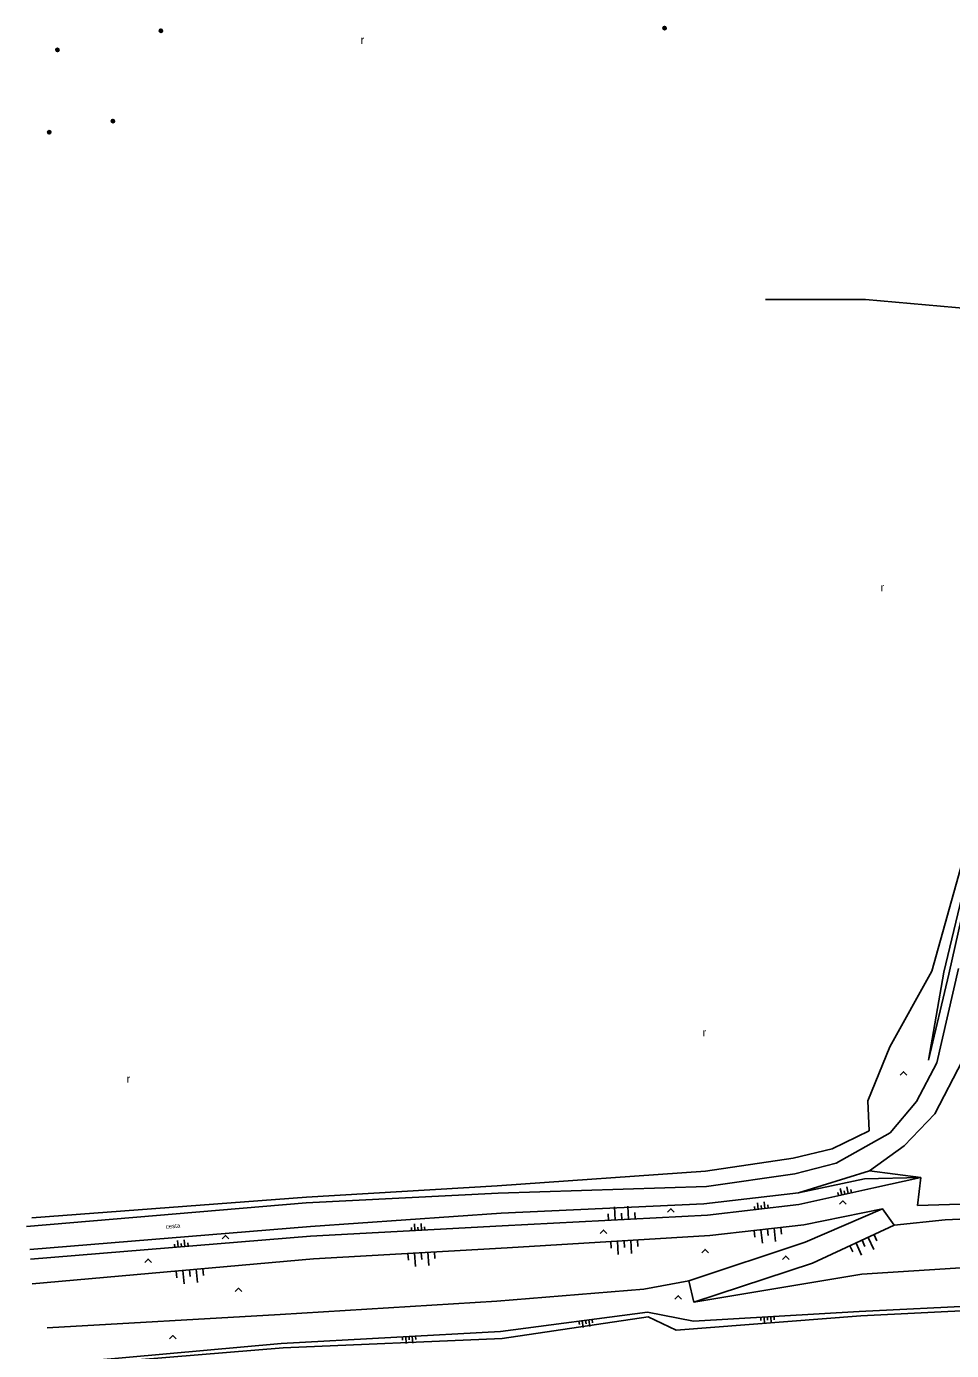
# Model space of a CAD drawing. Extents: x -539515 to -538098, y -1182060 to -1180157.
# Drawn here: x -539389.7 to -539250.9, y -1181057.1 to -1180858.5 of the extents above; entities that cross this region are included whole.
import ezdxf

# ---------------------------------------------------------------- set-up
doc = ezdxf.new("R2010")
doc.units = 0
for name, color, linetype in [('Vrstva 11', 7, 'Continuous'), ('Vrstva 14', 7, 'Continuous'), ('Vrstva 15', 7, 'Continuous'), ('Vrstva 23', 7, 'Continuous'), ('Vrstva 25', 7, 'Continuous'), ('Vrstva 36', 7, 'Continuous'), ('Vrstva 40', 7, 'Continuous')]:
    doc.layers.add(name, color=color, linetype=linetype)

msp = doc.modelspace()

# ---------------------------------------------------------------- linework, layer by layer
at = {"layer": 'Vrstva 11'}
for p, q in [((-539253.09, -1181013.89), (-539249.85, -1180999.75)), ((-539253.41, -1181021.54), (-539249.22, -1181013.54)), ((-539256.16, -1181019.71), (-539253.09, -1181013.89)), ((-539260.07, -1181024.41), (-539256.16, -1181019.71)), ((-539258, -1181026.34), (-539253.41, -1181021.54)), ((-539268.18, -1181028.97), (-539260.07, -1181024.41)), ((-539263.19, -1181030.11), (-539258, -1181026.34)), ((-539274.39, -1181030.54), (-539268.18, -1181028.97)), ((-539287.64, -1181032.44), (-539274.39, -1181030.54)), ((-539273.85, -1181033.4), (-539263.19, -1181030.11)), ((-539263.19, -1181030.11), (-539255.51, -1181031.11)), ((-539255.51, -1181031.11), (-539255.97, -1181035.29)), ((-539347.72, -1181034.93), (-539318.9, -1181033.44)), ((-539318.9, -1181033.44), (-539287.64, -1181032.44)), ((-539288.05, -1181035.06), (-539273.85, -1181033.4)), ((-539389.7, -1181038.45), (-539347.72, -1181034.93)), ((-539318.46, -1181036.45), (-539288.05, -1181035.06)), ((-539255.97, -1181035.29), (-539241.07, -1181034.88)), ((-539347.1, -1181038.48), (-539318.46, -1181036.45)), ((-539389.2, -1181041.91), (-539347.1, -1181038.48))]:
    msp.add_line(p, q, dxfattribs=at)
at = {"layer": 'Vrstva 14'}
for p, q in [((-539251.28, -1181000.64), (-539247.49, -1180983.74)), ((-539248.12, -1180984.08), (-539252.02, -1181000.33)), ((-539252.02, -1181000.33), (-539254.36, -1181013.51)), ((-539254.36, -1181013.51), (-539251.28, -1181000.64)), ((-539273.85, -1181033.4), (-539263.94, -1181031.3)), ((-539263.94, -1181031.3), (-539255.51, -1181031.11)), ((-539255.51, -1181031.11), (-539262.56, -1181032.64)), ((-539262.56, -1181032.64), (-539273.81, -1181035.17)), ((-539273.81, -1181035.17), (-539287.49, -1181036.78)), ((-539287.49, -1181036.78), (-539318.31, -1181038.37)), ((-539273.06, -1181038.22), (-539261.26, -1181035.83)), ((-539261.26, -1181035.83), (-539272.83, -1181040.81)), ((-539261.26, -1181035.83), (-539259.47, -1181038.28)), ((-539251.86, -1181037.44), (-539241.41, -1181036.99)), ((-539318.31, -1181038.37), (-539347.06, -1181039.92)), ((-539287.13, -1181039.82), (-539273.06, -1181038.22)), ((-539271.73, -1181043.97), (-539259.47, -1181038.28)), ((-539259.47, -1181038.28), (-539251.86, -1181037.44)), ((-539347.06, -1181039.92), (-539389.11, -1181043.35)), ((-539317.57, -1181041.64), (-539287.13, -1181039.82)), ((-539272.83, -1181040.81), (-539290.29, -1181046.61)), ((-539388.84, -1181047.05), (-539346.61, -1181043.32)), ((-539346.61, -1181043.32), (-539317.57, -1181041.64)), ((-539289.54, -1181049.81), (-539271.73, -1181043.97)), ((-539264.35, -1181045.61), (-539238.51, -1181043.97)), ((-539290.29, -1181046.61), (-539297.04, -1181047.84)), ((-539289.54, -1181049.81), (-539290.29, -1181046.61)), ((-539289.54, -1181049.81), (-539264.35, -1181045.61)), ((-539297.04, -1181047.84), (-539319.1, -1181049.67)), ((-539319.1, -1181049.67), (-539351.64, -1181051.64)), ((-539296.52, -1181051.33), (-539318.59, -1181054.22)), ((-539289.62, -1181052.65), (-539296.52, -1181051.33)), ((-539264.76, -1181051.21), (-539289.62, -1181052.65)), ((-539238.92, -1181049.91), (-539264.76, -1181051.21)), ((-539264.52, -1181051.88), (-539241.23, -1181050.7)), ((-539351.64, -1181051.64), (-539386.59, -1181053.65)), ((-539318.34, -1181055.28), (-539296.41, -1181052)), ((-539296.41, -1181052), (-539292.2, -1181053.99)), ((-539292.2, -1181053.99), (-539264.52, -1181051.88)), ((-539318.59, -1181054.22), (-539351.48, -1181056)), ((-539351.2, -1181056.67), (-539318.34, -1181055.28)), ((-539351.48, -1181056), (-539385.87, -1181059.1)), ((-539385.79, -1181059.52), (-539351.2, -1181056.67))]:
    msp.add_line(p, q, dxfattribs=at)
at = {"layer": 'Vrstva 15'}
for p, q in [((-539267.859, -1181033.831), (-539267.968, -1181033.344)), ((-539267.371, -1181033.722), (-539267.59, -1181032.746)), ((-539266.883, -1181033.612), (-539266.993, -1181033.124)), ((-539266.395, -1181033.502), (-539266.615, -1181032.527)), ((-539265.907, -1181033.393), (-539266.017, -1181032.905)), ((-539299.362, -1181037.392), (-539299.465, -1181035.395)), ((-539280.384, -1181035.944), (-539280.443, -1181035.447)), ((-539279.888, -1181035.885), (-539280.004, -1181034.892)), ((-539279.391, -1181035.827), (-539279.449, -1181035.33)), ((-539278.894, -1181035.769), (-539279.011, -1181034.775)), ((-539278.398, -1181035.71), (-539278.456, -1181035.214)), ((-539302.358, -1181037.547), (-539302.41, -1181036.548)), ((-539301.36, -1181037.496), (-539301.463, -1181035.498)), ((-539300.361, -1181037.444), (-539300.413, -1181036.445)), ((-539298.364, -1181037.341), (-539298.415, -1181036.342)), ((-539331.92, -1181039.104), (-539331.946, -1181038.605)), ((-539331.42, -1181039.077), (-539331.474, -1181038.078)), ((-539330.921, -1181039.05), (-539330.948, -1181038.551)), ((-539330.422, -1181039.023), (-539330.476, -1181038.025)), ((-539329.922, -1181038.996), (-539329.949, -1181038.497)), ((-539280.492, -1181039.065), (-539280.379, -1181040.059)), ((-539279.499, -1181038.952), (-539279.273, -1181040.939)), ((-539278.505, -1181038.839), (-539278.392, -1181039.833)), ((-539277.511, -1181038.726), (-539277.285, -1181040.713)), ((-539276.518, -1181038.613), (-539276.405, -1181039.607)), ((-539367.43, -1181041.581), (-539367.47, -1181041.083)), ((-539366.931, -1181041.541), (-539367.013, -1181040.544)), ((-539366.433, -1181041.5), (-539366.474, -1181041.002)), ((-539365.935, -1181041.459), (-539366.016, -1181040.463)), ((-539365.436, -1181041.419), (-539365.477, -1181040.92)), ((-539302.016, -1181040.71), (-539301.957, -1181041.709)), ((-539301.018, -1181040.651), (-539300.899, -1181042.647)), ((-539300.02, -1181040.591), (-539299.96, -1181041.589)), ((-539299.022, -1181040.531), (-539298.902, -1181042.528)), ((-539298.024, -1181040.472), (-539297.964, -1181041.47)), ((-539266.128, -1181041.37), (-539265.707, -1181042.277)), ((-539265.221, -1181040.949), (-539264.379, -1181042.763)), ((-539264.314, -1181040.528), (-539263.893, -1181041.435)), ((-539263.407, -1181040.107), (-539262.565, -1181041.921)), ((-539262.5, -1181039.686), (-539262.079, -1181040.593)), ((-539332.45, -1181042.501), (-539332.392, -1181043.499)), ((-539331.451, -1181042.443), (-539331.336, -1181044.439)), ((-539330.453, -1181042.385), (-539330.395, -1181043.383)), ((-539329.455, -1181042.327), (-539329.339, -1181044.324)), ((-539328.456, -1181042.269), (-539328.399, -1181043.268)), ((-539367.214, -1181045.14), (-539367.126, -1181046.136)), ((-539366.218, -1181045.052), (-539366.042, -1181047.044)), ((-539365.222, -1181044.964), (-539365.134, -1181045.96)), ((-539364.226, -1181044.876), (-539364.05, -1181046.868)), ((-539363.23, -1181044.788), (-539363.142, -1181045.784)), ((-539306.794, -1181052.675), (-539306.729, -1181053.171)), ((-539306.298, -1181052.61), (-539306.168, -1181053.601)), ((-539305.802, -1181052.545), (-539305.737, -1181053.041)), ((-539305.306, -1181052.48), (-539305.176, -1181053.472)), ((-539304.81, -1181052.415), (-539304.746, -1181052.911)), ((-539279.51, -1181052.065), (-539279.481, -1181052.564)), ((-539279.011, -1181052.036), (-539278.953, -1181053.034)), ((-539278.512, -1181052.007), (-539278.483, -1181052.506)), ((-539278.013, -1181051.978), (-539277.955, -1181052.976)), ((-539277.514, -1181051.949), (-539277.485, -1181052.448)), ((-539333.296, -1181055.016), (-539333.269, -1181055.515)), ((-539332.796, -1181054.989), (-539332.742, -1181055.988)), ((-539332.297, -1181054.962), (-539332.27, -1181055.461)), ((-539331.798, -1181054.935), (-539331.744, -1181055.934)), ((-539331.298, -1181054.908), (-539331.271, -1181055.407))]:
    msp.add_line(p, q, dxfattribs=at)
at = {"layer": 'Vrstva 23'}
for p, q in [((-539278.78, -1180899.44), (-539263.81, -1180899.44)), ((-539263.81, -1180899.44), (-539248.02, -1180900.82)), ((-539249.22, -1180983.7), (-539253.85, -1181000.15)), ((-539253.85, -1181000.15), (-539260.13, -1181011.53)), ((-539260.13, -1181011.53), (-539263.45, -1181019.62)), ((-539263.45, -1181019.62), (-539263.24, -1181024.13)), ((-539263.24, -1181024.13), (-539268.82, -1181026.8)), ((-539268.82, -1181026.8), (-539274.67, -1181028.21)), ((-539274.67, -1181028.21), (-539287.79, -1181030.14)), ((-539287.79, -1181030.14), (-539319.06, -1181032.34)), ((-539319.06, -1181032.34), (-539347.68, -1181034.04)), ((-539347.68, -1181034.04), (-539388.88, -1181037.17))]:
    msp.add_line(p, q, dxfattribs=at)
at = {"layer": 'Vrstva 25'}
for centre, radius in [((-539293.94, -1180858.74), 0.25), ((-539293.94, -1180858.74), 0.2), ((-539293.94, -1180858.74), 0.15), ((-539293.94, -1180858.74), 0.1), ((-539293.94, -1180858.74), 0.05), ((-539369.52, -1180859.13), 0.25), ((-539369.52, -1180859.13), 0.2), ((-539369.52, -1180859.13), 0.15), ((-539369.52, -1180859.13), 0.1), ((-539369.52, -1180859.13), 0.05), ((-539385.052, -1180862.004), 0.25), ((-539385.052, -1180862.004), 0.2), ((-539385.052, -1180862.004), 0.15), ((-539385.052, -1180862.004), 0.1), ((-539385.052, -1180862.004), 0.05), ((-539376.73, -1180872.68), 0.25), ((-539376.73, -1180872.68), 0.2), ((-539376.73, -1180872.68), 0.15), ((-539376.73, -1180872.68), 0.1), ((-539386.281, -1180874.354), 0.25), ((-539386.281, -1180874.354), 0.2), ((-539386.281, -1180874.354), 0.15), ((-539386.281, -1180874.354), 0.1), ((-539386.281, -1180874.354), 0.05), ((-539376.73, -1180872.68), 0.05)]:
    msp.add_circle(centre, radius, dxfattribs=at)
at = {"layer": 'Vrstva 36'}
for points in [[(-539258.602, -1181015.747), (-539258.102, -1181015.247), (-539257.602, -1181015.747)], [(-539267.691, -1181035.128), (-539267.191, -1181034.628), (-539266.691, -1181035.128)], [(-539293.499, -1181036.297), (-539292.999, -1181035.797), (-539292.499, -1181036.297)], [(-539303.625, -1181039.488), (-539303.125, -1181038.988), (-539302.625, -1181039.488)], [(-539360.324, -1181040.298), (-539359.824, -1181039.798), (-539359.324, -1181040.298)], [(-539371.954, -1181043.853), (-539371.454, -1181043.353), (-539370.954, -1181043.853)], [(-539288.366, -1181042.399), (-539287.866, -1181041.899), (-539287.366, -1181042.399)], [(-539276.251, -1181043.396), (-539275.751, -1181042.896), (-539275.251, -1181043.396)], [(-539358.386, -1181048.216), (-539357.886, -1181047.716), (-539357.386, -1181048.216)], [(-539292.404, -1181049.347), (-539291.904, -1181048.847), (-539291.404, -1181049.347)], [(-539368.239, -1181055.326), (-539367.739, -1181054.826), (-539367.239, -1181055.326)]]:
    msp.add_lwpolyline(points, dxfattribs=at)

# ---------------------------------------------------------------- texts
for p in [(-539339.547, -1180861.108), (-539261.542, -1180943.213), (-539288.257, -1181009.96), (-539374.669, -1181016.91)]:
    msp.add_text('r', height=1.2, dxfattribs=at).set_placement(p)
at = {"layer": 'Vrstva 40'}
msp.add_text('cesta', height=0.65, rotation=4.65775, dxfattribs=at).set_placement((-539368.759, -1181038.8))

doc.saveas('drawing.dxf')
